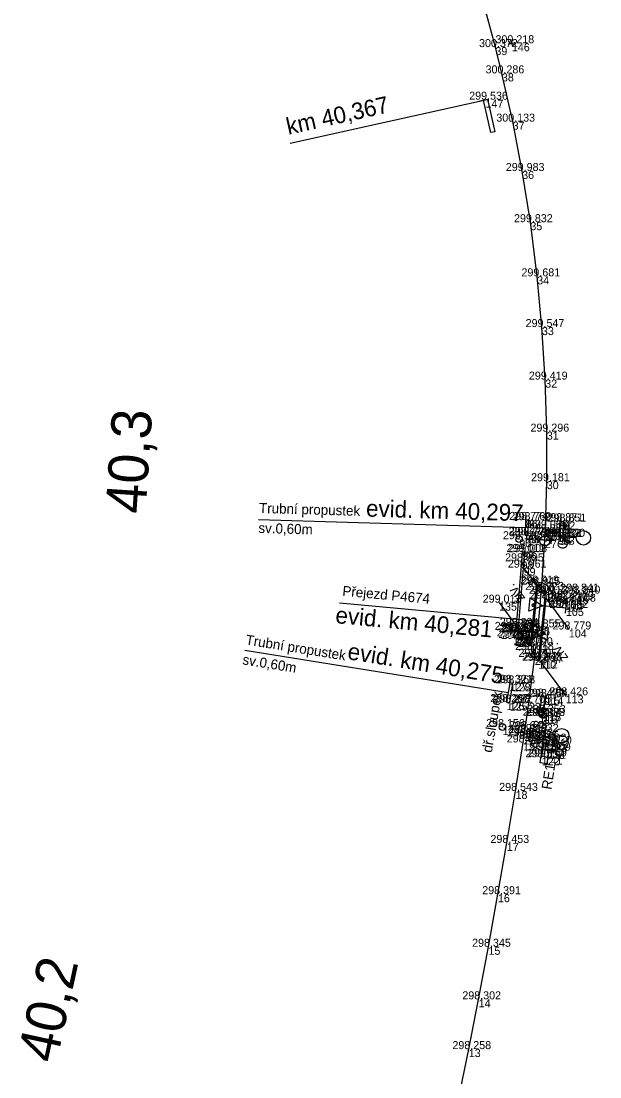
# Model space of a CAD drawing. Extents: x -684938 to -684389, y -1007777 to -1006471.
# Drawn here: x -684554.8 to -684468, y -1007124.9 to -1006966.7 of the extents above; entities that cross this region are included whole.
import ezdxf

# ---------------------------------------------------------------- set-up
doc = ezdxf.new("R2010")
doc.units = 0
for name, color, linetype in [('Vrstva 1', 7, 'Continuous'), ('Vrstva 12', 7, 'Continuous'), ('Vrstva 13', 7, 'Continuous'), ('Vrstva 19', 7, 'Continuous'), ('Vrstva 25', 7, 'Continuous'), ('Vrstva 3', 7, 'Continuous'), ('Vrstva 33', 7, 'Continuous'), ('Vrstva 4', 7, 'Continuous'), ('Vrstva 43', 7, 'Continuous'), ('Vrstva 50', 7, 'Continuous'), ('Vrstva 51', 7, 'Continuous'), ('Vrstva 60', 7, 'Continuous'), ('Vrstva 61', 7, 'Continuous'), ('Vrstva 63', 7, 'Continuous'), ('Vrstva 7', 7, 'Continuous'), ('Vrstva 9', 7, 'Continuous')]:
    doc.layers.add(name, color=color, linetype=linetype)

msp = doc.modelspace()

# ---------------------------------------------------------------- linework, layer by layer
at = {"layer": 'Vrstva 1'}
msp.add_lwpolyline([(-684489.29, -1007128.53), (-684487.68, -1007120.78), (-684486.2, -1007113.32), (-684484.73, -1007105.44), (-684483.31, -1007097.56), (-684481.98, -1007089.88), (-684480.67, -1007082.08), (-684479.54, -1007074.82), (-684479.4, -1007073.91), (-684479.32, -1007073.39), (-684479.23, -1007072.83), (-684478.66, -1007068.88), (-684477.78, -1007061.99), (-684477.29, -1007057.57), (-684476.77, -1007051.98), (-684476.28, -1007044.49), (-684476.22, -1007043.32), (-684476.19, -1007042.72), (-684475.99, -1007035.67), (-684475.98, -1007028.24), (-684476.22, -1007020.44), (-684476.71, -1007012.57), (-684477.42, -1007004.97), (-684478.45, -1006996.85), (-684479.68, -1006989.18), (-684481.1, -1006981.78), (-684482.71, -1006974.55), (-684483.69, -1006970.61), (-684485.64, -1006963.4)], dxfattribs=at)
at = {"layer": 'Vrstva 12'}
msp.add_line((-684476.74, -1007077.05), (-684476.39, -1007074.71), dxfattribs=at)
at = {"layer": 'Vrstva 13'}
msp.add_line((-684480.77, -1007059.15), (-684480.27, -1007058.25), dxfattribs=at)
msp.add_lwpolyline([(-684481.04, -1007058.94), (-684480.63, -1007058.2), (-684480.27, -1007058.25), (-684480.37, -1007059.3)], dxfattribs=at)
at = {"layer": 'Vrstva 19'}
for p, q in [((-684519.18, -1007041.42), (-684479.2, -1007042.62)), ((-684521.27, -1007061), (-684481.78, -1007067.33))]:
    msp.add_line(p, q, dxfattribs=at)
for points in [[(-684478.82, -1007043.78), (-684478.66, -1007041.51), (-684479.16, -1007041.47), (-684479.23, -1007043.77), (-684478.82, -1007043.78)], [(-684474.07, -1007044.01), (-684473.99, -1007041.66), (-684473.51, -1007041.72), (-684473.59, -1007043.99), (-684474.07, -1007044.01)], [(-684473.33, -1007053.7), (-684471.62, -1007052.22), (-684471.31, -1007052.52), (-684473.01, -1007054.03), (-684473.33, -1007053.7)], [(-684481.54, -1007068.84), (-684481.08, -1007065.97), (-684481.55, -1007065.89), (-684482.01, -1007068.77), (-684481.54, -1007068.84)], [(-684477.11, -1007070.79), (-684476.67, -1007067.95), (-684476.2, -1007068.02), (-684476.61, -1007070.86), (-684477.11, -1007070.79)]]:
    msp.add_lwpolyline(points, dxfattribs=at)
at = {"layer": 'Vrstva 25'}
for points in [[(-684475.99, -1007078), (-684476.98, -1007077.85), (-684476.67, -1007075.87), (-684475.69, -1007076.03), (-684475.99, -1007078)], [(-684475.4, -1007077.12), (-684476.39, -1007076.97), (-684476.08, -1007074.99), (-684475.09, -1007075.15), (-684475.4, -1007077.12)]]:
    msp.add_lwpolyline(points, dxfattribs=at)
at = {"layer": 'Vrstva 3'}
for p, q in [((-684477.31, -1007044.92), (-684477.24, -1007043.92)), ((-684475.31, -1007045.05), (-684475.24, -1007044.06)), ((-684474.33, -1007043.97), (-684471.58, -1007044.1)), ((-684477.27, -1007044.42), (-684475.28, -1007044.55)), ((-684480.39, -1007073.73), (-684480.24, -1007072.74)), ((-684480.31, -1007073.24), (-684478.33, -1007073.53)), ((-684478.41, -1007074.03), (-684478.26, -1007073.04)), ((-684477.67, -1007074.23), (-684474.94, -1007074.64)), ((-684477.56, -1007073.25), (-684474.83, -1007073.65))]:
    msp.add_line(p, q, dxfattribs=at)
for points in [[(-684472.23, -1007043.37), (-684474.33, -1007043.97), (-684472.3, -1007044.75)], [(-684475.41, -1007072.87), (-684477.56, -1007073.25), (-684475.61, -1007074.23)], [(-684475.52, -1007073.86), (-684477.67, -1007074.23), (-684475.72, -1007075.22)]]:
    msp.add_lwpolyline(points, dxfattribs=at)
for centre in [(-684470.49, -1007044.15), (-684473.75, -1007073.81), (-684473.87, -1007074.81)]:
    msp.add_circle(centre, 1.08, dxfattribs=at)
at = {"layer": 'Vrstva 33'}
for p, q in [((-684476.17, -1007075.48), (-684476.02, -1007074.49)), ((-684476.09, -1007074.99), (-684475.11, -1007075.14))]:
    msp.add_line(p, q, dxfattribs=at)
msp.add_lwpolyline([(-684476.74, -1007075.9), (-684476.44, -1007073.93), (-684474.46, -1007074.22), (-684474.76, -1007076.2), (-684476.74, -1007075.9)], dxfattribs=at)
at = {"layer": 'Vrstva 4'}
for p, q in [((-684507.07, -1007053.89), (-684477.2, -1007056.65)), ((-684477.79, -1007054.44), (-684478.1, -1007054.07)), ((-684473.19, -1007055.45), (-684473.04, -1007053.9)), ((-684481.25, -1007057.18), (-684481.43, -1007058.72)), ((-684476.67, -1007058.26), (-684476.37, -1007058.65))]:
    msp.add_line(p, q, dxfattribs=at)
for points in [[(-684478.28, -1007060.96), (-684477.33, -1007051.23), (-684476.22, -1007052.54), (-684477.26, -1007062.58), (-684478.28, -1007060.96)], [(-684473.12, -1007054.67), (-684476.58, -1007054.35), (-684478.67, -1007055.15), (-684478.49, -1007053.16), (-684476.58, -1007054.35)], [(-684481.34, -1007057.95), (-684477.88, -1007058.33), (-684475.78, -1007057.58), (-684475.99, -1007059.56), (-684477.88, -1007058.33)]]:
    msp.add_lwpolyline(points, dxfattribs=at)
for centre in [(-684477.94, -1007054.25), (-684476.52, -1007058.45)]:
    msp.add_circle(centre, 0.248, dxfattribs=at)
at = {"layer": 'Vrstva 43'}
msp.add_lwpolyline([(-684480.27, -1007058.25), (-684479.46, -1007048.63), (-684479.3, -1007046.31), (-684479.66, -1007046.26), (-684479.78, -1007047.68), (-684480.58, -1007057.36), (-684480.63, -1007058.2), (-684480.27, -1007058.25)], dxfattribs=at)
at = {"layer": 'Vrstva 50'}
msp.add_line((-684482.62, -1007072.46), (-684482.63, -1007072.55), dxfattribs=at)
msp.add_circle((-684482.62, -1007072.51), 0.5, dxfattribs=at)
at = {"layer": 'Vrstva 51'}
for points in [[(-684483.14, -1007053.87), (-684480.58, -1007057.36), (-684480.21, -1007058.09), (-684478.44, -1007060.26), (-684477.49, -1007051.03), (-684479.46, -1007048.63)], [(-684473.15, -1007067.76), (-684477.02, -1007062.52), (-684476.07, -1007053.27), (-684472.68, -1007057.89)]]:
    msp.add_lwpolyline(points, dxfattribs=at)
at = {"layer": 'Vrstva 60'}
for p, q in [((-684481.22, -1006970.03), (-684481.22, -1006970.03)), ((-684483.69, -1006970.61), (-684483.69, -1006970.61)), ((-684482.71, -1006974.55), (-684482.71, -1006974.55)), ((-684485.17, -1006978.49), (-684485.17, -1006978.49)), ((-684481.1, -1006981.78), (-684481.1, -1006981.78)), ((-684479.68, -1006989.18), (-684479.68, -1006989.18)), ((-684478.45, -1006996.85), (-684478.45, -1006996.85)), ((-684477.42, -1007004.97), (-684477.42, -1007004.97)), ((-684476.71, -1007012.57), (-684476.71, -1007012.57)), ((-684476.22, -1007020.44), (-684476.22, -1007020.44)), ((-684475.98, -1007028.24), (-684475.98, -1007028.24)), ((-684475.99, -1007035.67), (-684475.99, -1007035.67)), ((-684479.16, -1007041.47), (-684479.16, -1007041.47)), ((-684478.66, -1007041.51), (-684478.66, -1007041.51)), ((-684476.19, -1007042.72), (-684476.19, -1007042.72)), ((-684473.99, -1007041.66), (-684473.99, -1007041.66)), ((-684473.51, -1007041.72), (-684473.51, -1007041.72)), ((-684480.12, -1007044.36), (-684480.12, -1007044.36)), ((-684479.23, -1007043.77), (-684479.23, -1007043.77)), ((-684478.82, -1007043.78), (-684478.82, -1007043.78)), ((-684476.22, -1007043.32), (-684476.22, -1007043.32)), ((-684474.33, -1007043.97), (-684474.33, -1007043.97)), ((-684474.07, -1007044.01), (-684474.07, -1007044.01)), ((-684473.59, -1007043.99), (-684473.59, -1007043.99)), ((-684476.28, -1007044.49), (-684476.28, -1007044.49)), ((-684479.66, -1007046.26), (-684479.66, -1007046.26)), ((-684479.3, -1007046.31), (-684479.3, -1007046.31)), ((-684479.78, -1007047.68), (-684479.78, -1007047.68)), ((-684479.46, -1007048.63), (-684479.46, -1007048.63)), ((-684477.49, -1007051.03), (-684477.49, -1007051.03)), ((-684477.33, -1007051.23), (-684477.33, -1007051.23)), ((-684476.77, -1007051.98), (-684476.77, -1007051.98)), ((-684471.62, -1007052.22), (-684471.62, -1007052.22)), ((-684483.14, -1007053.87), (-684483.14, -1007053.87)), ((-684476.22, -1007052.54), (-684476.22, -1007052.54)), ((-684476.07, -1007053.27), (-684476.07, -1007053.27)), ((-684473.33, -1007053.7), (-684473.33, -1007053.7)), ((-684471.31, -1007052.52), (-684471.31, -1007052.52)), ((-684473.12, -1007054.67), (-684473.12, -1007054.67)), ((-684473.01, -1007054.03), (-684473.01, -1007054.03)), ((-684481.34, -1007057.95), (-684481.34, -1007057.95)), ((-684480.63, -1007058.2), (-684480.63, -1007058.2)), ((-684480.58, -1007057.36), (-684480.58, -1007057.36)), ((-684480.27, -1007058.25), (-684480.27, -1007058.25)), ((-684480.21, -1007058.09), (-684480.21, -1007058.09)), ((-684477.29, -1007057.57), (-684477.29, -1007057.57)), ((-684472.68, -1007057.89), (-684472.68, -1007057.89)), ((-684481.04, -1007058.94), (-684481.04, -1007058.94)), ((-684480.77, -1007059.15), (-684480.77, -1007059.15)), ((-684480.37, -1007059.3), (-684480.37, -1007059.3)), ((-684478.44, -1007060.26), (-684478.44, -1007060.26)), ((-684478.28, -1007060.96), (-684478.28, -1007060.96)), ((-684477.78, -1007061.99), (-684477.78, -1007061.99)), ((-684477.26, -1007062.58), (-684477.26, -1007062.58)), ((-684477.02, -1007062.52), (-684477.02, -1007062.52)), ((-684481.55, -1007065.89), (-684481.55, -1007065.89)), ((-684481.08, -1007065.97), (-684481.08, -1007065.97)), ((-684476.67, -1007067.95), (-684476.67, -1007067.95)), ((-684476.2, -1007068.02), (-684476.2, -1007068.02)), ((-684473.15, -1007067.76), (-684473.15, -1007067.76)), ((-684482.01, -1007068.77), (-684482.01, -1007068.77)), ((-684481.54, -1007068.84), (-684481.54, -1007068.84)), ((-684478.66, -1007068.88), (-684478.66, -1007068.88)), ((-684477.11, -1007070.79), (-684477.11, -1007070.79)), ((-684476.61, -1007070.86), (-684476.61, -1007070.86)), ((-684476.51, -1007070.39), (-684476.51, -1007070.39)), ((-684482.62, -1007072.51), (-684482.62, -1007072.51)), ((-684479.23, -1007072.83), (-684479.23, -1007072.83)), ((-684479.4, -1007073.91), (-684479.4, -1007073.91)), ((-684479.32, -1007073.39), (-684479.32, -1007073.39)), ((-684477.67, -1007074.23), (-684477.67, -1007074.23)), ((-684477.56, -1007073.25), (-684477.56, -1007073.25)), ((-684479.54, -1007074.82), (-684479.54, -1007074.82)), ((-684476.39, -1007074.71), (-684476.39, -1007074.71)), ((-684475.6, -1007075.06), (-684475.6, -1007075.06)), ((-684476.74, -1007077.05), (-684476.74, -1007077.05)), ((-684476.33, -1007076.94), (-684476.33, -1007076.94)), ((-684475.74, -1007076.06), (-684475.74, -1007076.06)), ((-684480.67, -1007082.08), (-684480.67, -1007082.08)), ((-684481.98, -1007089.88), (-684481.98, -1007089.88)), ((-684483.31, -1007097.56), (-684483.31, -1007097.56)), ((-684484.73, -1007105.44), (-684484.73, -1007105.44)), ((-684486.2, -1007113.32), (-684486.2, -1007113.32)), ((-684487.68, -1007120.78), (-684487.68, -1007120.78))]:
    msp.add_line(p, q, dxfattribs=at)
at = {"layer": 'Vrstva 63'}
for p, q in [((-684476.34, -1007070.26), (-684476.78, -1007069.67)), ((-684476.1, -1007070.08), (-684476.44, -1007069.63)), ((-684477.12, -1007070.84), (-684476.5, -1007070.39)), ((-684476.5, -1007070.39), (-684476.96, -1007069.78)), ((-684476.55, -1007071.15), (-684476.9, -1007070.68)), ((-684476.22, -1007071.1), (-684476.66, -1007070.5)), ((-684475.89, -1007069.93), (-684476.5, -1007070.39)), ((-684476.5, -1007070.39), (-684476.04, -1007071))]:
    msp.add_line(p, q, dxfattribs=at)
msp.add_circle((-684476.5, -1007070.39), 0.764, dxfattribs=at)
for start, end in [(36.8703, 126.7638), (216.4195, 306.7375)]:
    msp.add_arc((-684476.5, -1007070.39), 0.765, start, end, dxfattribs=at)
at = {"layer": 'Vrstva 7'}
for p, q in [((-684481.71, -1006970.15), (-684480.74, -1006969.91)), ((-684481.1, -1006970.51), (-684481.34, -1006969.54)), ((-684480.12, -1007044.41), (-684480.11, -1007044.31))]:
    msp.add_line(p, q, dxfattribs=at)
for centre, radius in [((-684480.12, -1007044.36), 0.5), ((-684476.28, -1007044.61), 0.75)]:
    msp.add_circle(centre, radius, dxfattribs=at)
at = {"layer": 'Vrstva 9'}
msp.add_line((-684514.45, -1006985.02), (-684485.17, -1006978.49), dxfattribs=at)
msp.add_lwpolyline([(-684486.05, -1006978.68), (-684485.46, -1006978.55), (-684484.88, -1006978.42), (-684483.79, -1006983.3), (-684484.37, -1006983.43), (-684485.46, -1006978.55)], dxfattribs=at)

# ---------------------------------------------------------------- texts
at = {"layer": 'Vrstva 19'}
for s, height, rotation, p in [('Trubní propustek', 1.5, 358.2772, (-684519.14, -1007040.42)), ('evid. km 40,297', 2.5, 358.2772, (-684503.1, -1007040.96)), ('sv.0,60m', 1.5, 358.2772, (-684519.23, -1007043.41)), ('Trubní propustek', 1.5, 350.9004, (-684521.21, -1007060.14)), ('evid. km 40,275', 2.5, 350.9004, (-684505.97, -1007062.33)), ('sv.0,60m', 1.5, 350.9004, (-684521.68, -1007063.1))]:
    msp.add_text(s, height=height, rotation=rotation, dxfattribs=at).set_placement(p)
at = {"layer": 'Vrstva 25'}
for s, p in [('k.s.', (-684473.61, -1007077.46)), ('RE1', (-684475.3, -1007081.96))]:
    msp.add_text(s, height=1.5, rotation=81.1596, dxfattribs=at).set_placement(p)
at = {"layer": 'Vrstva 3'}
for s, rotation, p in [('C', 87.2947, (-684472.9, -1007045.9)), ('B', 81.817, (-684476.59, -1007072.87)), ('A', 81.512, (-684477.05, -1007076.01))]:
    msp.add_text(s, height=1.5, rotation=rotation, dxfattribs=at).set_placement(p)
at = {"layer": 'Vrstva 4'}
for s, height, p in [('Přejezd P4674', 1.5, (-684506.67, -1007052.83)), ('evid. km 40,281', 2.5, (-684507.74, -1007056.93))]:
    msp.add_text(s, height=height, rotation=354.7233, dxfattribs=at).set_placement(p)
at = {"layer": 'Vrstva 50'}
msp.add_text('dř.sloupek', height=1.5, rotation=80.1558, dxfattribs=at).set_placement((-684484.23, -1007076.41))
at = {"layer": 'Vrstva 51'}
for rotation, p in [(129.3777, (-684479.13, -1007053.2)), (126.4268, (-684472.69, -1007062.13))]:
    msp.add_text('živ.', height=1.5, rotation=rotation, dxfattribs=at).set_placement(p)
at = {"layer": 'Vrstva 60'}
for s, p in [('146', (-684481.22, -1006971.23)), ('39', (-684483.69, -1006971.81)), ('38', (-684482.71, -1006975.75)), ('147', (-684485.17, -1006979.69)), ('37', (-684481.1, -1006982.98)), ('36', (-684479.68, -1006990.38)), ('35', (-684478.45, -1006998.05)), ('34', (-684477.42, -1007006.17)), ('33', (-684476.71, -1007013.77)), ('32', (-684476.22, -1007021.64)), ('31', (-684475.98, -1007029.44)), ('30', (-684475.99, -1007036.86)), ('86', (-684479.16, -1007042.67)), ('87', (-684478.66, -1007042.71)), ('29', (-684476.19, -1007043.93)), ('91', (-684473.99, -1007042.86)), ('92', (-684473.51, -1007042.93)), ('90', (-684480.12, -1007045.56)), ('89', (-684479.23, -1007044.96)), ('88', (-684478.82, -1007044.98)), ('28', (-684476.22, -1007044.52)), ('95', (-684474.33, -1007045.17)), ('94', (-684474.07, -1007045.21)), ('93', (-684473.59, -1007045.19)), ('27', (-684476.28, -1007045.69)), ('97', (-684479.66, -1007047.46)), ('96', (-684479.3, -1007047.51)), ('98', (-684479.78, -1007048.88)), ('99', (-684479.46, -1007049.83)), ('100', (-684477.49, -1007052.23)), ('101', (-684477.33, -1007052.43)), ('26', (-684476.77, -1007053.18)), ('109', (-684471.62, -1007053.42)), ('135', (-684483.14, -1007055.07)), ('102', (-684476.22, -1007053.74)), ('103', (-684476.07, -1007054.47)), ('106', (-684473.33, -1007054.9)), ('108', (-684471.31, -1007053.72)), ('105', (-684473.12, -1007055.87)), ('107', (-684473.01, -1007055.23)), ('131', (-684481.34, -1007059.15)), ('130', (-684480.63, -1007059.4)), ('134', (-684480.58, -1007058.56)), ('129', (-684480.27, -1007059.45)), ('133', (-684480.21, -1007059.29)), ('25', (-684477.29, -1007058.77)), ('104', (-684472.68, -1007059.09)), ('136', (-684481.04, -1007060.14)), ('137', (-684480.77, -1007060.35)), ('138', (-684480.37, -1007060.5)), ('132', (-684478.44, -1007061.46)), ('111', (-684478.28, -1007062.17)), ('24', (-684477.78, -1007063.19)), ('110', (-684477.26, -1007063.78)), ('112', (-684477.02, -1007063.72)), ('127', (-684481.55, -1007067.09)), ('128', (-684481.08, -1007067.17)), ('115', (-684476.67, -1007069.15)), ('114', (-684476.2, -1007069.22)), ('113', (-684473.15, -1007068.96)), ('126', (-684482.01, -1007069.97)), ('125', (-684481.54, -1007070.04)), ('23', (-684478.66, -1007070.08)), ('116', (-684477.11, -1007071.99)), ('117', (-684476.61, -1007072.07)), ('118', (-684476.51, -1007071.59)), ('124', (-684482.62, -1007073.71)), ('22', (-684479.23, -1007074.03)), ('20', (-684479.4, -1007075.11)), ('21', (-684479.32, -1007074.59)), ('120', (-684477.67, -1007075.44)), ('119', (-684477.56, -1007074.45)), ('19', (-684479.54, -1007076.02)), ('121', (-684476.39, -1007075.91)), ('123', (-684475.6, -1007076.26)), ('122', (-684476.74, -1007078.25)), ('141', (-684476.33, -1007078.14)), ('151', (-684475.74, -1007077.26)), ('18', (-684480.67, -1007083.28)), ('17', (-684481.98, -1007091.08)), ('16', (-684483.31, -1007098.76)), ('15', (-684484.73, -1007106.64)), ('14', (-684486.2, -1007114.52)), ('13', (-684487.68, -1007121.97))]:
    msp.add_text(s, height=1.2, dxfattribs=at).set_placement(p)
at = {"layer": 'Vrstva 61'}
for s, p in [('300.372', (-684486.14, -1006970.61)), ('300.218', (-684483.68, -1006970.03)), ('300.286', (-684485.16, -1006974.55)), ('299.536', (-684487.62, -1006978.49)), ('300.133', (-684483.55, -1006981.78)), ('299.983', (-684482.13, -1006989.18)), ('299.832', (-684480.9, -1006996.85)), ('299.681', (-684479.78, -1007004.97)), ('299.547', (-684479.16, -1007012.57)), ('299.419', (-684478.67, -1007020.44)), ('299.296', (-684478.43, -1007028.24)), ('299.181', (-684478.34, -1007035.67)), ('298.774', (-684481.61, -1007041.47)), ('298.769', (-684481.11, -1007041.51)), ('298.871', (-684476.34, -1007041.66)), ('298.851', (-684475.87, -1007041.72)), ('298.779', (-684481.69, -1007043.77)), ('298.778', (-684481.27, -1007043.78)), ('299.054', (-684478.67, -1007043.32)), ('299.066', (-684478.65, -1007042.72)), ('299.081', (-684476.69, -1007043.97)), ('298.821', (-684476.43, -1007044.01)), ('298.820', (-684476.04, -1007043.99)), ('299.102', (-684482.56, -1007044.36)), ('299.033', (-684478.73, -1007044.49)), ('299.011', (-684482.02, -1007046.26)), ('299.008', (-684481.75, -1007046.31)), ('298.995', (-684482.24, -1007047.68)), ('298.961', (-684481.82, -1007048.63)), ('298.919', (-684479.95, -1007051.03)), ('298.945', (-684479.79, -1007051.23)), ('298.923', (-684479.22, -1007051.98)), ('299.013', (-684478.68, -1007052.54)), ('298.982', (-684478.52, -1007053.27)), ('298.841', (-684473.98, -1007052.22)), ('298.840', (-684473.76, -1007052.52)), ('299.012', (-684485.59, -1007053.87)), ('298.877', (-684475.78, -1007053.7)), ('298.962', (-684475.57, -1007054.67)), ('298.915', (-684475.47, -1007054.03)), ('298.883', (-684483.79, -1007057.95)), ('298.894', (-684483.08, -1007058.2)), ('298.894', (-684483.03, -1007057.36)), ('298.893', (-684482.72, -1007058.25)), ('298.875', (-684482.67, -1007058.09)), ('298.855', (-684479.74, -1007057.57)), ('298.779', (-684475.13, -1007057.89)), ('298.822', (-684483.49, -1007058.94)), ('298.442', (-684483.22, -1007059.15)), ('298.724', (-684482.82, -1007059.3)), ('298.790', (-684480.89, -1007060.26)), ('298.818', (-684480.73, -1007060.96)), ('298.795', (-684480.23, -1007061.99)), ('298.862', (-684479.7, -1007062.58)), ('298.848', (-684479.47, -1007062.52)), ('298.321', (-684483.9, -1007065.89)), ('298.368', (-684483.54, -1007065.97)), ('298.426', (-684475.6, -1007067.76)), ('298.267', (-684484.46, -1007068.77)), ('298.282', (-684483.99, -1007068.84)), ('298.705', (-684481.12, -1007068.88)), ('298.472', (-684479.12, -1007067.95)), ('298.464', (-684478.65, -1007068.02)), ('298.404', (-684479.56, -1007070.79)), ('298.383', (-684479.06, -1007070.86)), ('298.353', (-684478.96, -1007070.39)), ('298.156', (-684485.08, -1007072.51)), ('298.630', (-684481.85, -1007073.91)), ('298.630', (-684481.77, -1007073.39)), ('298.646', (-684481.68, -1007072.83)), ('298.632', (-684480.01, -1007073.25)), ('298.627', (-684481.99, -1007074.82)), ('298.595', (-684480.12, -1007074.23)), ('298.492', (-684478.84, -1007074.71)), ('299.470', (-684478.05, -1007075.06)), ('298.557', (-684479.19, -1007077.05)), ('299.769', (-684478.79, -1007076.94)), ('298.509', (-684478.2, -1007076.06)), ('298.543', (-684483.12, -1007082.08)), ('298.453', (-684484.43, -1007089.88)), ('298.391', (-684485.66, -1007097.56)), ('298.345', (-684487.18, -1007105.44)), ('298.302', (-684488.65, -1007113.32)), ('298.258', (-684490.13, -1007120.78))]:
    msp.add_text(s, height=1.2, dxfattribs=at).set_placement(p)
at = {"layer": 'Vrstva 7'}
for s, rotation, p in [('40,3', 86.2138, (-684536.15, -1007040.65)), ('40,2', 77.7139, (-684549.5, -1007123.04))]:
    msp.add_text(s, height=6, rotation=rotation, dxfattribs=at).set_placement(p)
at = {"layer": 'Vrstva 9'}
msp.add_text('km 40,367', height=2.5, rotation=12.5724, dxfattribs=at).set_placement((-684514.73, -1006983.76))

doc.saveas('drawing.dxf')
